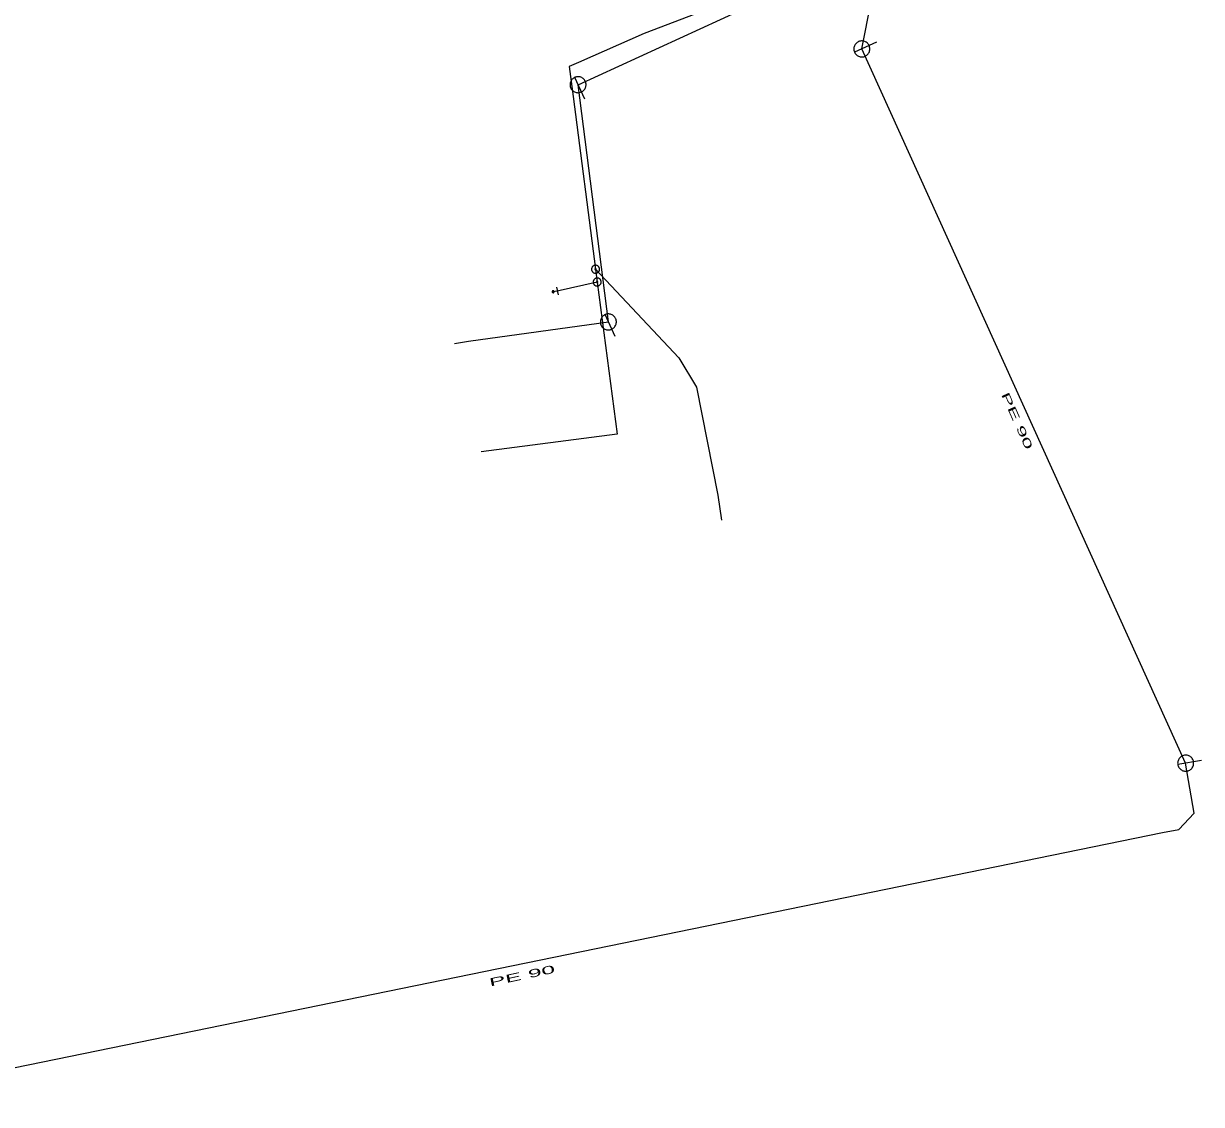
# Model space of a CAD drawing. Extents: x -807203 to -805207, y -993656 to -992505.
# Drawn here: x -806773.5 to -806626.3, y -993187.3 to -993052.3 of the extents above; entities that cross this region are included whole.
import ezdxf

# ---------------------------------------------------------------- set-up
doc = ezdxf.new("R2010")
doc.units = 0
doc.header["$LTSCALE"] = 0.4
for name, color, linetype, lineweight in [('1', 7, 'Continuous', 13), ('11', 7, 'Continuous', 13), ('13', 7, 'Continuous', 13), ('14', 7, 'Continuous', 25), ('22', 7, 'Continuous', 13), ('34', 7, 'Continuous', 13), ('47', 7, 'Continuous', 13), ('9', 7, 'Continuous', 13)]:
    doc.layers.add(name, color=color, linetype=linetype, lineweight=lineweight)

msp = doc.modelspace()

# ---------------------------------------------------------------- linework, layer by layer
at = {"layer": '11'}
for points in [[(-806700.399, -993089.539), (-806704.189, -993059.899), (-806673.68, -993045.89)], [(-806719.647, -993092.23), (-806717.87, -993091.96), (-806700.399, -993089.539)]]:
    msp.add_lwpolyline(points, dxfattribs=at)
at = {"layer": '13'}
msp.add_line((-806702.003, -993082.953), (-806701.796, -993084.551), dxfattribs=at)
for points in [[(-806684.207, -993048.995), (-806695.936, -993053.515), (-806704.138, -993057.129), (-806705.287, -993057.636), (-806704.804, -993061.366), (-806702.003, -993082.953)], [(-806702.003, -993082.953), (-806691.6, -993094.03), (-806689.379, -993097.67), (-806686.719, -993111.199), (-806686.267, -993114.317)], [(-806701.796, -993084.551), (-806699.285, -993103.567), (-806716.298, -993105.752)]]:
    msp.add_lwpolyline(points, dxfattribs=at)
at = {"layer": '14', "lineweight": 13}
for p, q in [((-806701.796, -993084.551), (-806706.779, -993085.679)), ((-806706.779, -993085.679), (-806707.299, -993085.759))]:
    msp.add_line(p, q, dxfattribs=at)
at = {"layer": '14'}
msp.add_lwpolyline([(-806797.184, -993187.298), (-806631.149, -993153.329), (-806629.079, -993152.949), (-806627.19, -993150.92), (-806628.243, -993144.662), (-806668.719, -993055.43), (-806665.21, -993037.78)], dxfattribs=at)
at = {"layer": '22'}
for p, q in [((-806666.897, -993054.603), (-806669.629, -993055.842)), ((-806703.354, -993061.716), (-806704.606, -993058.99)), ((-806699.564, -993091.356), (-806700.816, -993088.63)), ((-806626.27, -993144.329), (-806629.228, -993144.827))]:
    msp.add_line(p, q, dxfattribs=at)
for points in [[(-806669.131, -993054.519), (-806669.228, -993054.569), (-806669.319, -993054.63), (-806669.403, -993054.701), (-806669.478, -993054.779), (-806669.545, -993054.867), (-806669.602, -993054.96), (-806669.647, -993055.06), (-806669.682, -993055.164), (-806669.706, -993055.271), (-806669.717, -993055.379), (-806669.717, -993055.489), (-806669.703, -993055.598), (-806669.679, -993055.705), (-806669.643, -993055.808), (-806669.596, -993055.908), (-806669.538, -993056), (-806669.472, -993056.087), (-806669.395, -993056.166), (-806669.31, -993056.235), (-806669.219, -993056.295), (-806669.121, -993056.344), (-806669.019, -993056.383), (-806668.912, -993056.41), (-806668.804, -993056.426), (-806668.695, -993056.429), (-806668.586, -993056.42), (-806668.478, -993056.4), (-806668.374, -993056.368), (-806668.273, -993056.324), (-806668.177, -993056.27), (-806668.089, -993056.207), (-806668.008, -993056.133), (-806667.935, -993056.051), (-806667.871, -993055.962), (-806667.818, -993055.866), (-806667.776, -993055.765), (-806667.745, -993055.66), (-806667.726, -993055.552), (-806667.718, -993055.443), (-806667.723, -993055.334), (-806667.739, -993055.226), (-806667.767, -993055.12), (-806667.807, -993055.017), (-806667.857, -993054.92), (-806667.918, -993054.829), (-806667.988, -993054.746), (-806668.068, -993054.67), (-806668.155, -993054.603), (-806668.249, -993054.547), (-806668.348, -993054.5), (-806668.452, -993054.465), (-806668.559, -993054.442), (-806668.667, -993054.43), (-806668.777, -993054.431), (-806668.885, -993054.443), (-806668.993, -993054.468), (-806669.096, -993054.504)], [(-806703.28, -993059.482), (-806703.33, -993059.385), (-806703.392, -993059.294), (-806703.463, -993059.211), (-806703.542, -993059.136), (-806703.63, -993059.069), (-806703.724, -993059.013), (-806703.824, -993058.968), (-806703.927, -993058.934), (-806704.035, -993058.911), (-806704.143, -993058.9), (-806704.253, -993058.901), (-806704.362, -993058.915), (-806704.468, -993058.939), (-806704.572, -993058.976), (-806704.671, -993059.023), (-806704.763, -993059.081), (-806704.85, -993059.149), (-806704.928, -993059.225), (-806704.997, -993059.311), (-806705.056, -993059.402), (-806705.105, -993059.5), (-806705.143, -993059.602), (-806705.17, -993059.709), (-806705.185, -993059.818), (-806705.188, -993059.927), (-806705.179, -993060.036), (-806705.158, -993060.144), (-806705.125, -993060.248), (-806705.081, -993060.349), (-806705.027, -993060.443), (-806704.963, -993060.532), (-806704.889, -993060.612), (-806704.807, -993060.685), (-806704.717, -993060.748), (-806704.62, -993060.801), (-806704.52, -993060.842), (-806704.414, -993060.873), (-806704.307, -993060.892), (-806704.198, -993060.899), (-806704.088, -993060.894), (-806703.98, -993060.877), (-806703.874, -993060.849), (-806703.772, -993060.808), (-806703.675, -993060.757), (-806703.585, -993060.696), (-806703.501, -993060.626), (-806703.426, -993060.546), (-806703.359, -993060.458), (-806703.303, -993060.364), (-806703.258, -993060.265), (-806703.223, -993060.161), (-806703.201, -993060.054), (-806703.189, -993059.945), (-806703.191, -993059.836), (-806703.203, -993059.727), (-806703.228, -993059.62), (-806703.265, -993059.517)], [(-806699.49, -993089.122), (-806699.54, -993089.025), (-806699.602, -993088.934), (-806699.673, -993088.851), (-806699.752, -993088.776), (-806699.84, -993088.709), (-806699.934, -993088.653), (-806700.034, -993088.608), (-806700.137, -993088.574), (-806700.245, -993088.551), (-806700.353, -993088.54), (-806700.463, -993088.541), (-806700.572, -993088.555), (-806700.678, -993088.579), (-806700.782, -993088.616), (-806700.881, -993088.663), (-806700.973, -993088.721), (-806701.06, -993088.789), (-806701.138, -993088.865), (-806701.207, -993088.951), (-806701.266, -993089.042), (-806701.315, -993089.14), (-806701.353, -993089.242), (-806701.38, -993089.349), (-806701.395, -993089.458), (-806701.398, -993089.567), (-806701.389, -993089.676), (-806701.368, -993089.784), (-806701.335, -993089.888), (-806701.291, -993089.989), (-806701.237, -993090.083), (-806701.173, -993090.172), (-806701.099, -993090.252), (-806701.017, -993090.325), (-806700.927, -993090.388), (-806700.83, -993090.441), (-806700.73, -993090.482), (-806700.624, -993090.513), (-806700.517, -993090.532), (-806700.408, -993090.539), (-806700.298, -993090.534), (-806700.19, -993090.517), (-806700.084, -993090.489), (-806699.982, -993090.448), (-806699.885, -993090.397), (-806699.795, -993090.336), (-806699.711, -993090.266), (-806699.636, -993090.186), (-806699.569, -993090.098), (-806699.513, -993090.004), (-806699.468, -993089.905), (-806699.433, -993089.801), (-806699.411, -993089.694), (-806699.399, -993089.585), (-806699.401, -993089.476), (-806699.413, -993089.367), (-806699.438, -993089.26), (-806699.475, -993089.157)], [(-806628.408, -993143.675), (-806628.515, -993143.699), (-806628.618, -993143.735), (-806628.718, -993143.782), (-806628.811, -993143.838), (-806628.898, -993143.906), (-806628.976, -993143.982), (-806629.046, -993144.067), (-806629.106, -993144.158), (-806629.156, -993144.256), (-806629.195, -993144.357), (-806629.222, -993144.464), (-806629.238, -993144.573), (-806629.242, -993144.682), (-806629.233, -993144.791), (-806629.213, -993144.899), (-806629.181, -993145.003), (-806629.139, -993145.105), (-806629.085, -993145.2), (-806629.021, -993145.288), (-806628.948, -993145.37), (-806628.866, -993145.443), (-806628.777, -993145.506), (-806628.681, -993145.56), (-806628.58, -993145.603), (-806628.476, -993145.634), (-806628.368, -993145.653), (-806628.258, -993145.661), (-806628.149, -993145.657), (-806628.041, -993145.641), (-806627.935, -993145.613), (-806627.833, -993145.574), (-806627.736, -993145.523), (-806627.645, -993145.463), (-806627.56, -993145.393), (-806627.484, -993145.314), (-806627.418, -993145.227), (-806627.36, -993145.134), (-806627.314, -993145.035), (-806627.279, -993144.931), (-806627.255, -993144.824), (-806627.243, -993144.715), (-806627.243, -993144.606), (-806627.256, -993144.496), (-806627.28, -993144.39), (-806627.315, -993144.286), (-806627.361, -993144.188), (-806627.419, -993144.094), (-806627.486, -993144.007), (-806627.562, -993143.928), (-806627.646, -993143.858), (-806627.737, -993143.798), (-806627.835, -993143.748), (-806627.937, -993143.709), (-806628.043, -993143.682), (-806628.151, -993143.665), (-806628.261, -993143.662), (-806628.37, -993143.67)]]:
    msp.add_lwpolyline(points, close=True, dxfattribs=at)
at = {"layer": '34'}
msp.add_line((-806706.889, -993085.191), (-806706.669, -993086.166), dxfattribs=at)
at = {"layer": '47'}
for points in [[(-806701.938, -993083.448), (-806701.887, -993083.439), (-806701.836, -993083.424), (-806701.789, -993083.404), (-806701.742, -993083.38), (-806701.699, -993083.35), (-806701.659, -993083.315), (-806701.624, -993083.277), (-806701.592, -993083.236), (-806701.564, -993083.192), (-806701.541, -993083.145), (-806701.523, -993083.095), (-806701.512, -993083.044), (-806701.504, -993082.993), (-806701.503, -993082.94), (-806701.507, -993082.888), (-806701.516, -993082.837), (-806701.531, -993082.786), (-806701.551, -993082.738), (-806701.575, -993082.692), (-806701.605, -993082.649), (-806701.64, -993082.609), (-806701.678, -993082.573), (-806701.719, -993082.541), (-806701.763, -993082.513), (-806701.81, -993082.491), (-806701.86, -993082.473), (-806701.911, -993082.461), (-806701.962, -993082.454), (-806702.015, -993082.453), (-806702.067, -993082.457), (-806702.118, -993082.466), (-806702.169, -993082.481), (-806702.217, -993082.5), (-806702.263, -993082.525), (-806702.306, -993082.555), (-806702.346, -993082.589), (-806702.383, -993082.627), (-806702.414, -993082.668), (-806702.442, -993082.713), (-806702.464, -993082.76), (-806702.482, -993082.81), (-806702.494, -993082.86), (-806702.501, -993082.912), (-806702.502, -993082.965), (-806702.498, -993083.017), (-806702.489, -993083.068), (-806702.474, -993083.119), (-806702.455, -993083.166), (-806702.43, -993083.213), (-806702.4, -993083.256), (-806702.366, -993083.296), (-806702.328, -993083.332), (-806702.287, -993083.364), (-806702.242, -993083.391), (-806702.195, -993083.414), (-806702.145, -993083.432), (-806702.095, -993083.443), (-806702.043, -993083.451), (-806701.99, -993083.452)], [(-806701.992, -993083.034), (-806701.983, -993083.033), (-806701.975, -993083.03), (-806701.968, -993083.027), (-806701.96, -993083.023), (-806701.953, -993083.018), (-806701.946, -993083.012), (-806701.94, -993083.006), (-806701.935, -993082.999), (-806701.931, -993082.992), (-806701.927, -993082.984), (-806701.924, -993082.976), (-806701.922, -993082.967), (-806701.921, -993082.959), (-806701.92, -993082.951), (-806701.921, -993082.942), (-806701.922, -993082.933), (-806701.925, -993082.925), (-806701.928, -993082.918), (-806701.932, -993082.91), (-806701.937, -993082.903), (-806701.943, -993082.896), (-806701.949, -993082.89), (-806701.956, -993082.885), (-806701.964, -993082.88), (-806701.971, -993082.877), (-806701.979, -993082.874), (-806701.988, -993082.872), (-806701.996, -993082.871), (-806702.004, -993082.87), (-806702.013, -993082.871), (-806702.022, -993082.872), (-806702.03, -993082.875), (-806702.037, -993082.878), (-806702.045, -993082.882), (-806702.052, -993082.887), (-806702.059, -993082.892), (-806702.065, -993082.899), (-806702.07, -993082.906), (-806702.075, -993082.914), (-806702.078, -993082.921), (-806702.081, -993082.929), (-806702.083, -993082.938), (-806702.084, -993082.946), (-806702.085, -993082.954), (-806702.084, -993082.963), (-806702.083, -993082.972), (-806702.08, -993082.98), (-806702.077, -993082.987), (-806702.073, -993082.995), (-806702.068, -993083.002), (-806702.063, -993083.009), (-806702.056, -993083.015), (-806702.049, -993083.02), (-806702.042, -993083.024), (-806702.034, -993083.028), (-806702.026, -993083.031), (-806702.017, -993083.033), (-806702.009, -993083.034), (-806702.001, -993083.035)], [(-806701.731, -993085.046), (-806701.68, -993085.037), (-806701.63, -993085.022), (-806701.582, -993085.002), (-806701.535, -993084.978), (-806701.492, -993084.948), (-806701.452, -993084.913), (-806701.417, -993084.876), (-806701.385, -993084.834), (-806701.357, -993084.79), (-806701.334, -993084.743), (-806701.316, -993084.693), (-806701.305, -993084.642), (-806701.297, -993084.591), (-806701.296, -993084.538), (-806701.3, -993084.486), (-806701.309, -993084.435), (-806701.324, -993084.385), (-806701.344, -993084.336), (-806701.368, -993084.29), (-806701.398, -993084.247), (-806701.433, -993084.207), (-806701.471, -993084.171), (-806701.512, -993084.139), (-806701.556, -993084.111), (-806701.603, -993084.089), (-806701.653, -993084.071), (-806701.704, -993084.059), (-806701.755, -993084.052), (-806701.808, -993084.051), (-806701.86, -993084.055), (-806701.911, -993084.064), (-806701.961, -993084.079), (-806702.01, -993084.098), (-806702.056, -993084.123), (-806702.099, -993084.153), (-806702.139, -993084.187), (-806702.176, -993084.225), (-806702.207, -993084.266), (-806702.235, -993084.311), (-806702.257, -993084.358), (-806702.275, -993084.408), (-806702.287, -993084.458), (-806702.294, -993084.51), (-806702.295, -993084.563), (-806702.291, -993084.615), (-806702.282, -993084.666), (-806702.267, -993084.716), (-806702.248, -993084.764), (-806702.223, -993084.811), (-806702.193, -993084.854), (-806702.159, -993084.894), (-806702.122, -993084.93), (-806702.08, -993084.961), (-806702.035, -993084.989), (-806701.988, -993085.012), (-806701.938, -993085.03), (-806701.888, -993085.041), (-806701.836, -993085.049), (-806701.783, -993085.05)], [(-806701.785, -993084.632), (-806701.776, -993084.631), (-806701.768, -993084.628), (-806701.761, -993084.625), (-806701.753, -993084.621), (-806701.746, -993084.616), (-806701.739, -993084.61), (-806701.733, -993084.604), (-806701.728, -993084.597), (-806701.724, -993084.59), (-806701.72, -993084.582), (-806701.717, -993084.574), (-806701.715, -993084.565), (-806701.714, -993084.557), (-806701.713, -993084.549), (-806701.714, -993084.54), (-806701.715, -993084.531), (-806701.718, -993084.523), (-806701.721, -993084.516), (-806701.725, -993084.508), (-806701.73, -993084.501), (-806701.736, -993084.494), (-806701.742, -993084.488), (-806701.749, -993084.483), (-806701.757, -993084.478), (-806701.764, -993084.475), (-806701.772, -993084.472), (-806701.781, -993084.47), (-806701.789, -993084.469), (-806701.797, -993084.468), (-806701.806, -993084.469), (-806701.815, -993084.47), (-806701.823, -993084.473), (-806701.83, -993084.476), (-806701.838, -993084.48), (-806701.845, -993084.485), (-806701.852, -993084.49), (-806701.858, -993084.497), (-806701.863, -993084.504), (-806701.868, -993084.512), (-806701.871, -993084.519), (-806701.874, -993084.527), (-806701.876, -993084.536), (-806701.877, -993084.544), (-806701.878, -993084.552), (-806701.877, -993084.561), (-806701.876, -993084.57), (-806701.873, -993084.578), (-806701.87, -993084.585), (-806701.866, -993084.593), (-806701.861, -993084.6), (-806701.856, -993084.607), (-806701.849, -993084.613), (-806701.842, -993084.618), (-806701.835, -993084.622), (-806701.827, -993084.626), (-806701.819, -993084.629), (-806701.81, -993084.631), (-806701.802, -993084.632), (-806701.794, -993084.633)]]:
    msp.add_lwpolyline(points, close=True, dxfattribs=at)
at = {"layer": '9'}
for points in [[(-806707.425, -993085.759), (-806707.425, -993085.772), (-806707.423, -993085.785), (-806707.42, -993085.798), (-806707.415, -993085.81), (-806707.409, -993085.822), (-806707.402, -993085.833), (-806707.394, -993085.843), (-806707.384, -993085.853), (-806707.374, -993085.861), (-806707.363, -993085.868), (-806707.351, -993085.874), (-806707.339, -993085.879), (-806707.326, -993085.882), (-806707.313, -993085.884), (-806707.3, -993085.886), (-806707.287, -993085.885), (-806707.274, -993085.883), (-806707.261, -993085.88), (-806707.249, -993085.875), (-806707.237, -993085.869), (-806707.226, -993085.862), (-806707.216, -993085.854), (-806707.206, -993085.844), (-806707.198, -993085.834), (-806707.191, -993085.823), (-806707.185, -993085.811), (-806707.18, -993085.799), (-806707.177, -993085.786), (-806707.175, -993085.773), (-806707.173, -993085.76), (-806707.174, -993085.747), (-806707.176, -993085.734), (-806707.179, -993085.721), (-806707.184, -993085.709), (-806707.19, -993085.697), (-806707.197, -993085.686), (-806707.205, -993085.676), (-806707.215, -993085.666), (-806707.225, -993085.658), (-806707.236, -993085.651), (-806707.248, -993085.645), (-806707.26, -993085.64), (-806707.273, -993085.637), (-806707.286, -993085.635), (-806707.299, -993085.634), (-806707.312, -993085.634), (-806707.325, -993085.636), (-806707.338, -993085.639), (-806707.35, -993085.644), (-806707.362, -993085.65), (-806707.373, -993085.657), (-806707.383, -993085.665), (-806707.393, -993085.675), (-806707.401, -993085.685), (-806707.408, -993085.696), (-806707.414, -993085.708), (-806707.419, -993085.72), (-806707.422, -993085.733), (-806707.424, -993085.746)], [(-806707.405, -993085.759), (-806707.406, -993085.77), (-806707.404, -993085.781), (-806707.401, -993085.792), (-806707.397, -993085.802), (-806707.392, -993085.812), (-806707.386, -993085.821), (-806707.379, -993085.83), (-806707.371, -993085.838), (-806707.362, -993085.845), (-806707.353, -993085.851), (-806707.343, -993085.856), (-806707.333, -993085.86), (-806707.322, -993085.863), (-806707.311, -993085.866), (-806707.3, -993085.866), (-806707.289, -993085.866), (-806707.278, -993085.864), (-806707.267, -993085.861), (-806707.257, -993085.857), (-806707.247, -993085.852), (-806707.238, -993085.846), (-806707.229, -993085.839), (-806707.221, -993085.831), (-806707.214, -993085.822), (-806707.208, -993085.813), (-806707.203, -993085.803), (-806707.199, -993085.793), (-806707.196, -993085.782), (-806707.194, -993085.771), (-806707.193, -993085.76), (-806707.193, -993085.749), (-806707.195, -993085.738), (-806707.198, -993085.727), (-806707.202, -993085.717), (-806707.207, -993085.707), (-806707.213, -993085.698), (-806707.22, -993085.689), (-806707.228, -993085.681), (-806707.237, -993085.674), (-806707.246, -993085.668), (-806707.256, -993085.663), (-806707.266, -993085.659), (-806707.277, -993085.656), (-806707.288, -993085.654), (-806707.299, -993085.654), (-806707.31, -993085.653), (-806707.321, -993085.655), (-806707.332, -993085.658), (-806707.342, -993085.662), (-806707.352, -993085.667), (-806707.361, -993085.673), (-806707.37, -993085.68), (-806707.378, -993085.688), (-806707.385, -993085.697), (-806707.391, -993085.706), (-806707.396, -993085.716), (-806707.4, -993085.726), (-806707.403, -993085.737), (-806707.405, -993085.748)], [(-806707.386, -993085.759), (-806707.386, -993085.768), (-806707.385, -993085.777), (-806707.382, -993085.786), (-806707.379, -993085.794), (-806707.375, -993085.802), (-806707.37, -993085.81), (-806707.364, -993085.817), (-806707.358, -993085.823), (-806707.351, -993085.829), (-806707.343, -993085.834), (-806707.335, -993085.838), (-806707.327, -993085.841), (-806707.318, -993085.844), (-806707.309, -993085.845), (-806707.3, -993085.847), (-806707.291, -993085.846), (-806707.282, -993085.845), (-806707.273, -993085.842), (-806707.265, -993085.839), (-806707.257, -993085.835), (-806707.249, -993085.83), (-806707.242, -993085.824), (-806707.236, -993085.818), (-806707.23, -993085.811), (-806707.225, -993085.803), (-806707.221, -993085.795), (-806707.218, -993085.787), (-806707.215, -993085.778), (-806707.214, -993085.769), (-806707.212, -993085.76), (-806707.213, -993085.751), (-806707.214, -993085.742), (-806707.217, -993085.733), (-806707.22, -993085.725), (-806707.224, -993085.717), (-806707.229, -993085.709), (-806707.235, -993085.702), (-806707.241, -993085.696), (-806707.248, -993085.69), (-806707.256, -993085.685), (-806707.264, -993085.681), (-806707.272, -993085.678), (-806707.281, -993085.675), (-806707.29, -993085.674), (-806707.299, -993085.673), (-806707.308, -993085.673), (-806707.317, -993085.674), (-806707.326, -993085.677), (-806707.334, -993085.68), (-806707.342, -993085.684), (-806707.35, -993085.689), (-806707.357, -993085.695), (-806707.363, -993085.701), (-806707.369, -993085.708), (-806707.374, -993085.716), (-806707.378, -993085.724), (-806707.381, -993085.732), (-806707.384, -993085.741), (-806707.385, -993085.75)], [(-806707.366, -993085.759), (-806707.366, -993085.766), (-806707.365, -993085.773), (-806707.364, -993085.78), (-806707.361, -993085.786), (-806707.358, -993085.792), (-806707.354, -993085.798), (-806707.35, -993085.804), (-806707.345, -993085.809), (-806707.339, -993085.813), (-806707.333, -993085.817), (-806707.327, -993085.82), (-806707.321, -993085.823), (-806707.314, -993085.824), (-806707.307, -993085.827), (-806707.3, -993085.827), (-806707.293, -993085.827), (-806707.286, -993085.825), (-806707.279, -993085.824), (-806707.273, -993085.821), (-806707.266, -993085.818), (-806707.261, -993085.814), (-806707.255, -993085.81), (-806707.25, -993085.805), (-806707.246, -993085.799), (-806707.242, -993085.793), (-806707.239, -993085.787), (-806707.236, -993085.781), (-806707.234, -993085.774), (-806707.233, -993085.767), (-806707.232, -993085.76), (-806707.232, -993085.753), (-806707.233, -993085.746), (-806707.235, -993085.739), (-806707.238, -993085.733), (-806707.241, -993085.726), (-806707.245, -993085.721), (-806707.249, -993085.715), (-806707.254, -993085.71), (-806707.26, -993085.706), (-806707.265, -993085.702), (-806707.272, -993085.699), (-806707.278, -993085.696), (-806707.285, -993085.694), (-806707.292, -993085.693), (-806707.299, -993085.693), (-806707.306, -993085.693), (-806707.313, -993085.693), (-806707.32, -993085.695), (-806707.326, -993085.698), (-806707.332, -993085.701), (-806707.338, -993085.705), (-806707.344, -993085.709), (-806707.349, -993085.714), (-806707.353, -993085.72), (-806707.357, -993085.725), (-806707.36, -993085.732), (-806707.363, -993085.738), (-806707.364, -993085.745), (-806707.366, -993085.752)], [(-806707.346, -993085.759), (-806707.346, -993085.764), (-806707.346, -993085.769), (-806707.345, -993085.774), (-806707.343, -993085.778), (-806707.341, -993085.783), (-806707.338, -993085.787), (-806707.335, -993085.79), (-806707.331, -993085.794), (-806707.328, -993085.797), (-806707.324, -993085.8), (-806707.319, -993085.802), (-806707.315, -993085.804), (-806707.31, -993085.805), (-806707.305, -993085.807), (-806707.3, -993085.807), (-806707.295, -993085.807), (-806707.29, -993085.806), (-806707.285, -993085.805), (-806707.281, -993085.803), (-806707.276, -993085.801), (-806707.272, -993085.798), (-806707.268, -993085.795), (-806707.265, -993085.791), (-806707.262, -993085.788), (-806707.259, -993085.784), (-806707.257, -993085.779), (-806707.255, -993085.775), (-806707.254, -993085.77), (-806707.253, -993085.765), (-806707.252, -993085.76), (-806707.252, -993085.755), (-806707.253, -993085.75), (-806707.254, -993085.745), (-806707.256, -993085.741), (-806707.258, -993085.736), (-806707.261, -993085.732), (-806707.264, -993085.728), (-806707.267, -993085.725), (-806707.271, -993085.722), (-806707.275, -993085.719), (-806707.28, -993085.717), (-806707.284, -993085.715), (-806707.289, -993085.714), (-806707.294, -993085.713), (-806707.299, -993085.713), (-806707.304, -993085.713), (-806707.309, -993085.714), (-806707.314, -993085.714), (-806707.318, -993085.716), (-806707.323, -993085.718), (-806707.327, -993085.721), (-806707.33, -993085.724), (-806707.334, -993085.727), (-806707.337, -993085.731), (-806707.34, -993085.735), (-806707.342, -993085.74), (-806707.344, -993085.744), (-806707.345, -993085.749), (-806707.346, -993085.754)], [(-806707.326, -993085.759), (-806707.326, -993085.762), (-806707.327, -993085.765), (-806707.326, -993085.767), (-806707.325, -993085.77), (-806707.324, -993085.773), (-806707.322, -993085.775), (-806707.32, -993085.777), (-806707.318, -993085.779), (-806707.316, -993085.781), (-806707.314, -993085.783), (-806707.311, -993085.785), (-806707.308, -993085.786), (-806707.306, -993085.786), (-806707.303, -993085.787), (-806707.3, -993085.787), (-806707.297, -993085.787), (-806707.294, -993085.787), (-806707.291, -993085.786), (-806707.289, -993085.785), (-806707.286, -993085.784), (-806707.284, -993085.782), (-806707.281, -993085.78), (-806707.279, -993085.778), (-806707.278, -993085.776), (-806707.276, -993085.774), (-806707.275, -993085.771), (-806707.273, -993085.768), (-806707.273, -993085.766), (-806707.272, -993085.763), (-806707.271, -993085.76), (-806707.272, -993085.757), (-806707.272, -993085.754), (-806707.273, -993085.751), (-806707.274, -993085.749), (-806707.275, -993085.746), (-806707.277, -993085.744), (-806707.278, -993085.741), (-806707.28, -993085.739), (-806707.283, -993085.738), (-806707.285, -993085.736), (-806707.288, -993085.735), (-806707.29, -993085.734), (-806707.293, -993085.733), (-806707.296, -993085.733), (-806707.299, -993085.732), (-806707.302, -993085.733), (-806707.305, -993085.732), (-806707.307, -993085.734), (-806707.31, -993085.734), (-806707.313, -993085.735), (-806707.315, -993085.737), (-806707.317, -993085.738), (-806707.319, -993085.74), (-806707.321, -993085.743), (-806707.323, -993085.745), (-806707.324, -993085.748), (-806707.325, -993085.75), (-806707.326, -993085.753), (-806707.326, -993085.756)], [(-806707.307, -993085.759), (-806707.307, -993085.761), (-806707.307, -993085.761), (-806707.306, -993085.761), (-806707.306, -993085.763), (-806707.307, -993085.764), (-806707.305, -993085.764), (-806707.305, -993085.764), (-806707.305, -993085.766), (-806707.305, -993085.766), (-806707.304, -993085.767), (-806707.302, -993085.767), (-806707.302, -993085.767), (-806707.302, -993085.768), (-806707.3, -993085.768), (-806707.3, -993085.768), (-806707.299, -993085.768), (-806707.298, -993085.768), (-806707.298, -993085.767), (-806707.297, -993085.767), (-806707.295, -993085.767), (-806707.295, -993085.766), (-806707.295, -993085.766), (-806707.294, -993085.765), (-806707.294, -993085.765), (-806707.292, -993085.764), (-806707.292, -993085.763), (-806707.291, -993085.762), (-806707.291, -993085.762), (-806707.291, -993085.761), (-806707.291, -993085.76), (-806707.291, -993085.759), (-806707.291, -993085.758), (-806707.291, -993085.758), (-806707.292, -993085.757), (-806707.292, -993085.756), (-806707.293, -993085.755), (-806707.293, -993085.755), (-806707.294, -993085.754), (-806707.294, -993085.754), (-806707.295, -993085.753), (-806707.296, -993085.753), (-806707.297, -993085.752), (-806707.297, -993085.752), (-806707.298, -993085.752), (-806707.299, -993085.752), (-806707.3, -993085.752), (-806707.301, -993085.752), (-806707.301, -993085.752), (-806707.302, -993085.753), (-806707.303, -993085.752), (-806707.304, -993085.754), (-806707.304, -993085.754), (-806707.305, -993085.754), (-806707.305, -993085.754), (-806707.306, -993085.756), (-806707.306, -993085.757), (-806707.306, -993085.758), (-806707.307, -993085.758), (-806707.307, -993085.759)]]:
    msp.add_lwpolyline(points, close=True, dxfattribs=at)

# ---------------------------------------------------------------- texts
at = {"layer": '1'}
for rotation, width, p in [(294, 2.1, (-806651.322, -993098.588)), (12, 2.3, (-806715.183, -993172.569))]:
    msp.add_text('PE 90 ', height=1, rotation=rotation, dxfattribs=dict(at, width=width)).set_placement(p)

doc.saveas('drawing.dxf')
